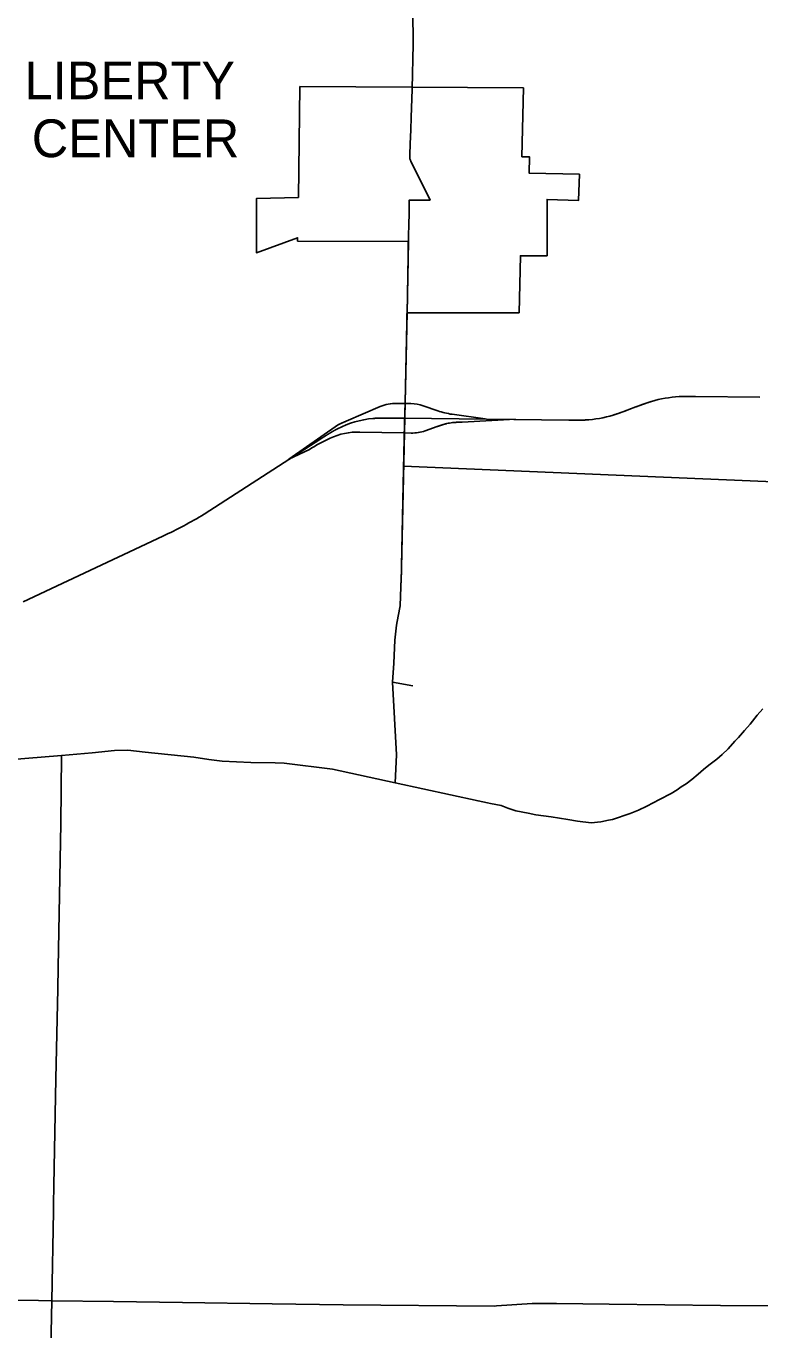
# Model space of a CAD drawing. Extents: x -62 to 810, y 0 to 440.
# Drawn here: x 358.3 to 408.1, y 261.1 to 349.6 of the extents above; entities that cross this region are included whole.
import ezdxf

# ---------------------------------------------------------------- set-up
doc = ezdxf.new("R2010")
doc.units = 0
for name, color, linetype in [('DV_X_Corp_Line', 7, 'Continuous'), ('GM_X_Corporation_Text', 7, 'Continuous'), ('GM_X_State_Route', 7, 'Continuous'), ('SH_Data', 7, 'Continuous'), ('SH_Text', 7, 'Continuous')]:
    doc.layers.add(name, color=color, linetype=linetype)

msp = doc.modelspace()

# ---------------------------------------------------------------- linework, layer by layer
at = {"layer": 'DV_X_Corp_Line'}
msp.add_lwpolyline([(376.707, 335.035), (376.714, 335.257), (373.916, 334.245), (373.932, 337.925), (376.768, 337.998), (376.868, 345.517), (392.056, 345.433), (391.959, 340.759), (392.478, 340.748), (392.455, 339.639), (395.861, 339.566), (395.808, 337.796), (393.665, 337.864), (393.664, 334.036), (391.854, 334.033), (391.762, 330.17), (384.151, 330.165), (384.247, 334.998)], close=True, dxfattribs=at)
at = {"layer": 'GM_X_State_Route'}
for p, q in [((383.455, 324.016), (383.975, 324.006)), ((383.975, 324.006), (384.416, 323.997)), ((403.764, 324.485), (408.134, 324.432)), ((380.022, 322.81), (382.331, 323.797)), ((385.238, 323.853), (386.235, 323.514)), ((389.467, 322.957), (387.217, 323.272)), ((399.222, 323.592), (399.69, 323.769)), ((376.124, 320.23), (379.501, 322.578)), ((383.956, 323.009), (395.151, 322.875)), ((385.378, 322.152), (386.208, 322.441)), ((387.908, 322.736), (391.52, 322.937)), ((370.359, 316.484), (378.304, 321.613)), ((380.948, 322.07), (383.934, 322.011)), ((383.934, 322.011), (384.43, 322.002)), ((377.523, 320.881), (376.124, 320.23)), ((358.077, 310.544), (367.562, 315)), ((384.536, 304.847), (383.167, 305.08))]:
    msp.add_line(p, q, dxfattribs=at)
for points in [[(384.503, 345.373), (384.58, 348.411), (384.534, 352.965), (384.815, 368.019), (385.213, 389.406)], [(384.381, 340.524), (384.377, 340.535), (384.339, 340.625), (384.34, 340.882), (384.368, 341.642), (384.402, 342.577), (384.433, 343.44), (384.502, 345.322), (384.503, 345.373)], [(385.724, 337.8), (385.724, 337.8), (385.106, 339.053), (384.8, 339.673), (384.417, 340.449), (384.387, 340.509), (384.381, 340.524)], [(384.24, 334.635), (384.286, 336.915), (384.304, 337.821), (385.724, 337.8)], [(384.228, 334.029), (384.229, 334.113), (384.24, 334.635)], [(384.173, 331.298), (384.175, 331.39), (384.228, 334.029)], [(384.149, 330.085), (384.151, 330.179), (384.173, 331.298)], [(383.742, 311.819), (383.743, 311.857), (383.899, 318.509), (383.985, 322.653), (384, 323.397), (384.014, 324.054), (384.138, 329.513), (384.149, 330.085)], [(383.167, 305.08), (383.244, 306.376), (383.331, 307.934), (383.433, 308.966), (383.557, 309.562), (383.679, 310.268), (383.736, 311.569), (383.742, 311.819)], [(383.348, 298.264), (383.438, 300.159), (383.167, 305.08)], [(389.833, 296.853), (390.541, 296.707), (390.994, 296.536), (391.545, 296.348), (392.375, 296.186), (392.916, 296.08), (393.942, 295.943), (395.089, 295.763), (395.728, 295.658), (396.671, 295.54), (397.316, 295.608), (397.843, 295.72), (398.104, 295.775), (399.32, 296.172), (399.877, 296.409), (400.452, 296.68), (400.889, 296.896), (401.31, 297.112), (402.111, 297.529), (402.511, 297.769), (402.79, 297.974), (403.125, 298.187), (403.495, 298.484), (403.928, 298.843), (404.305, 299.163), (404.663, 299.46), (405.201, 299.869), (405.571, 300.183), (405.965, 300.571), (406.436, 301.09), (406.668, 301.326), (407.093, 301.817), (407.465, 302.245), (407.937, 302.849), (408.337, 303.272)], [(350.801, 300.622), (353.067, 300.321), (354.335, 300.101), (355.937, 299.736), (360.668, 300.11)], [(360.148, 270.819), (360.15, 270.917), (360.194, 273.339), (360.278, 278.152), (360.43, 284.278), (360.455, 285.73), (360.627, 295.47), (360.668, 300.11)], [(360.668, 300.11), (362.765, 300.302), (364.263, 300.439), (365.182, 300.461), (366.363, 300.347), (369.655, 300.006), (370.694, 299.838), (371.587, 299.714), (373.541, 299.642), (375.195, 299.607), (375.808, 299.587), (379.079, 299.172), (383.348, 298.264)], [(383.348, 298.264), (388.985, 297.028), (389.613, 296.898), (389.833, 296.853)], [(360.118, 269.153), (360.12, 269.262), (360.126, 269.596), (360.128, 269.733), (360.148, 270.819)], [(360.007, 263.095), (360.118, 269.153)], [(355.008, 263.139), (355.055, 263.138), (359.098, 263.103)], [(359.098, 263.103), (359.106, 263.103), (360.007, 263.095)], [(359.66, 220.968), (359.691, 227.727), (359.734, 232.912), (359.691, 233.115), (359.617, 233.258), (359.542, 233.389), (359.497, 233.555), (359.48, 233.903), (359.693, 247.954), (359.849, 255.51), (360.007, 263.095)], [(360.007, 263.095), (364.198, 263.037)], [(364.198, 263.037), (368.891, 262.972), (374.978, 262.881), (379.814, 262.808), (390.079, 262.732), (390.242, 262.754), (392.655, 262.906), (393.215, 262.916), (394.306, 262.896), (397.877, 262.859), (405.457, 262.782), (408.703, 262.749), (413.048, 262.725), (420.595, 262.684), (425.883, 262.655), (429.596, 262.616), (429.597, 262.616)]]:
    msp.add_lwpolyline(points, dxfattribs=at)
for centre, radius, start, end in [((383.401, 321.295), 2.722, 88.87, 113.16335), ((384.363, 321.276), 2.722, 71.23123, 88.87), ((403.1, 316.322), 8.165, 93.2557, 106.69439), ((388.141, 329.123), 5.924, 251.23123, 261.02199), ((395.812, 331.039), 8.165, 273.27836, 286.69439), ((382.419, 316.484), 6.532, 95.09336, 117.22501), ((387.6, 319.462), 3.266, 96.33912, 103.32164), ((383.452, 311.751), 10.886, 114.61118, 123.00153), ((380.856, 317.419), 4.653, 88.87, 114.61118), ((384.484, 324.72), 2.719, 268.87, 289.19664), ((353.674, 344.559), 32.659, 295.16667, 300.72373)]:
    msp.add_arc(centre, radius, start, end, dxfattribs=at)
for points in [[(399.69, 323.769), (399.704, 323.774), (399.718, 323.779), (399.732, 323.785), (399.747, 323.79), (399.761, 323.795), (399.775, 323.801), (399.79, 323.806), (399.804, 323.812), (399.818, 323.817), (399.832, 323.822), (399.847, 323.828), (399.861, 323.833), (399.875, 323.838), (399.889, 323.844), (399.904, 323.849), (399.918, 323.854), (399.932, 323.86), (399.947, 323.865), (399.961, 323.87), (399.975, 323.876), (399.99, 323.881), (400.004, 323.886), (400.018, 323.892), (400.032, 323.897), (400.047, 323.902), (400.061, 323.907), (400.075, 323.913), (400.09, 323.918), (400.104, 323.923), (400.118, 323.928), (400.133, 323.934), (400.147, 323.939), (400.161, 323.944), (400.176, 323.949), (400.19, 323.954), (400.204, 323.959), (400.219, 323.965), (400.233, 323.97), (400.248, 323.975), (400.262, 323.98), (400.276, 323.985), (400.291, 323.99), (400.305, 323.995), (400.319, 324), (400.334, 324.005), (400.348, 324.01), (400.363, 324.015), (400.377, 324.02), (400.391, 324.025), (400.406, 324.03), (400.42, 324.035), (400.435, 324.04), (400.449, 324.045), (400.464, 324.05), (400.478, 324.054), (400.493, 324.059), (400.507, 324.064), (400.522, 324.069), (400.536, 324.074), (400.551, 324.078), (400.565, 324.083), (400.58, 324.088), (400.594, 324.092), (400.609, 324.097), (400.623, 324.102), (400.638, 324.106), (400.652, 324.111), (400.667, 324.115), (400.681, 324.12), (400.696, 324.124), (400.711, 324.129), (400.725, 324.133), (400.74, 324.138), (400.754, 324.142)], [(402.636, 324.473), (402.651, 324.474), (402.667, 324.475), (402.682, 324.476), (402.697, 324.476), (402.712, 324.477), (402.727, 324.478), (402.743, 324.478), (402.758, 324.479), (402.773, 324.48), (402.788, 324.48), (402.804, 324.481), (402.819, 324.482), (402.834, 324.482), (402.849, 324.483), (402.865, 324.483), (402.88, 324.484), (402.895, 324.484), (402.91, 324.484), (402.926, 324.485), (402.941, 324.485), (402.956, 324.486), (402.971, 324.486), (402.987, 324.486), (403.002, 324.487), (403.017, 324.487), (403.032, 324.487), (403.048, 324.487), (403.063, 324.488), (403.078, 324.488), (403.093, 324.488), (403.109, 324.488), (403.124, 324.488), (403.139, 324.488), (403.154, 324.489), (403.17, 324.489), (403.185, 324.489), (403.2, 324.489), (403.215, 324.489), (403.231, 324.489), (403.246, 324.489), (403.261, 324.489), (403.276, 324.489), (403.292, 324.489), (403.307, 324.489), (403.322, 324.489), (403.337, 324.489), (403.353, 324.489), (403.368, 324.489), (403.383, 324.489), (403.398, 324.489), (403.414, 324.489), (403.429, 324.489), (403.444, 324.489), (403.459, 324.488), (403.475, 324.488), (403.49, 324.488), (403.505, 324.488), (403.52, 324.488), (403.536, 324.488), (403.551, 324.488), (403.566, 324.488), (403.581, 324.487), (403.597, 324.487), (403.612, 324.487), (403.627, 324.487), (403.642, 324.487), (403.658, 324.487), (403.673, 324.486), (403.688, 324.486), (403.703, 324.486), (403.719, 324.486), (403.734, 324.486), (403.749, 324.485), (403.764, 324.485)], [(398.158, 323.219), (398.172, 323.223), (398.187, 323.228), (398.201, 323.232), (398.216, 323.237), (398.23, 323.241), (398.245, 323.246), (398.26, 323.25), (398.274, 323.255), (398.289, 323.259), (398.303, 323.264), (398.318, 323.269), (398.332, 323.273), (398.347, 323.278), (398.361, 323.283), (398.376, 323.287), (398.39, 323.292), (398.405, 323.297), (398.419, 323.302), (398.434, 323.307), (398.448, 323.311), (398.463, 323.316), (398.477, 323.321), (398.491, 323.326), (398.506, 323.331), (398.52, 323.336), (398.535, 323.341), (398.549, 323.346), (398.564, 323.351), (398.578, 323.356), (398.592, 323.361), (398.607, 323.366), (398.621, 323.371), (398.636, 323.376), (398.65, 323.381), (398.664, 323.386), (398.679, 323.391), (398.693, 323.396), (398.707, 323.402), (398.722, 323.407), (398.736, 323.412), (398.75, 323.417), (398.765, 323.422), (398.779, 323.427), (398.794, 323.433), (398.808, 323.438), (398.822, 323.443), (398.836, 323.448), (398.851, 323.454), (398.865, 323.459), (398.879, 323.464), (398.894, 323.469), (398.908, 323.475), (398.922, 323.48), (398.937, 323.485), (398.951, 323.491), (398.965, 323.496), (398.98, 323.501), (398.994, 323.507), (399.008, 323.512), (399.022, 323.517), (399.037, 323.523), (399.051, 323.528), (399.065, 323.533), (399.08, 323.539), (399.094, 323.544), (399.108, 323.549), (399.122, 323.555), (399.137, 323.56), (399.151, 323.566), (399.165, 323.571), (399.179, 323.576), (399.194, 323.582), (399.208, 323.587), (399.222, 323.592)], [(378.304, 321.613), (378.318, 321.622), (378.333, 321.632), (378.348, 321.642), (378.363, 321.651), (378.378, 321.661), (378.393, 321.671), (378.408, 321.68), (378.423, 321.69), (378.438, 321.7), (378.453, 321.709), (378.468, 321.719), (378.483, 321.729), (378.498, 321.738), (378.513, 321.748), (378.528, 321.758), (378.543, 321.767), (378.557, 321.777), (378.572, 321.786), (378.587, 321.796), (378.602, 321.806), (378.617, 321.815), (378.632, 321.825), (378.647, 321.834), (378.662, 321.844), (378.678, 321.853), (378.693, 321.863), (378.708, 321.872), (378.723, 321.882), (378.738, 321.891), (378.753, 321.901), (378.768, 321.91), (378.783, 321.92), (378.798, 321.929), (378.813, 321.938), (378.828, 321.948), (378.843, 321.957), (378.859, 321.966), (378.874, 321.976), (378.889, 321.985), (378.904, 321.994), (378.919, 322.003), (378.935, 322.013), (378.95, 322.022), (378.965, 322.031), (378.98, 322.04), (378.996, 322.049), (379.011, 322.058), (379.026, 322.067), (379.042, 322.076), (379.057, 322.086), (379.072, 322.094), (379.088, 322.103), (379.103, 322.112), (379.118, 322.121), (379.134, 322.13), (379.149, 322.139), (379.165, 322.148), (379.18, 322.157), (379.196, 322.165), (379.211, 322.174), (379.227, 322.183), (379.242, 322.191), (379.258, 322.2), (379.274, 322.208), (379.289, 322.217), (379.305, 322.225), (379.321, 322.234), (379.336, 322.242), (379.352, 322.251), (379.368, 322.259), (379.383, 322.267), (379.399, 322.275), (379.415, 322.284), (379.431, 322.292)], [(379.501, 322.578), (379.508, 322.582), (379.515, 322.585), (379.522, 322.588), (379.529, 322.592), (379.536, 322.595), (379.543, 322.598), (379.55, 322.601), (379.557, 322.605), (379.564, 322.608), (379.571, 322.611), (379.578, 322.614), (379.585, 322.618), (379.592, 322.621), (379.599, 322.624), (379.606, 322.627), (379.613, 322.631), (379.62, 322.634), (379.627, 322.637), (379.634, 322.64), (379.641, 322.643), (379.648, 322.647), (379.655, 322.65), (379.662, 322.653), (379.669, 322.656), (379.676, 322.659), (379.683, 322.662), (379.69, 322.666), (379.697, 322.669), (379.704, 322.672), (379.711, 322.675), (379.718, 322.678), (379.725, 322.681), (379.732, 322.684), (379.74, 322.687), (379.747, 322.691), (379.754, 322.694), (379.761, 322.697), (379.768, 322.7), (379.775, 322.703), (379.782, 322.706), (379.789, 322.709), (379.796, 322.712), (379.803, 322.715), (379.81, 322.718), (379.817, 322.722), (379.824, 322.725), (379.831, 322.728), (379.838, 322.731), (379.845, 322.734), (379.852, 322.737), (379.86, 322.74), (379.867, 322.743), (379.874, 322.746), (379.881, 322.749), (379.888, 322.752), (379.895, 322.755), (379.902, 322.758), (379.909, 322.761), (379.916, 322.764), (379.923, 322.767), (379.93, 322.77), (379.937, 322.773), (379.944, 322.776), (379.951, 322.78), (379.959, 322.783), (379.966, 322.786), (379.973, 322.789), (379.98, 322.792), (379.987, 322.795), (379.994, 322.798), (380.001, 322.801), (380.008, 322.804), (380.015, 322.807), (380.022, 322.81)], [(381.839, 322.99), (381.857, 322.991), (381.874, 322.993), (381.892, 322.994), (381.91, 322.996), (381.928, 322.997), (381.945, 322.998), (381.963, 323), (381.981, 323.001), (381.999, 323.002), (382.016, 323.003), (382.034, 323.004), (382.052, 323.005), (382.07, 323.006), (382.088, 323.007), (382.105, 323.008), (382.123, 323.009), (382.141, 323.01), (382.159, 323.011), (382.176, 323.012), (382.194, 323.012), (382.212, 323.013), (382.23, 323.014), (382.247, 323.015), (382.265, 323.015), (382.283, 323.016), (382.301, 323.016), (382.319, 323.017), (382.336, 323.017), (382.354, 323.018), (382.372, 323.018), (382.39, 323.019), (382.408, 323.019), (382.425, 323.019), (382.443, 323.02), (382.461, 323.02), (382.479, 323.02), (382.497, 323.02), (382.514, 323.021), (382.532, 323.021), (382.55, 323.021), (382.568, 323.021), (382.585, 323.021), (382.603, 323.022), (382.621, 323.022), (382.639, 323.022), (382.657, 323.022), (382.674, 323.022), (382.692, 323.022), (382.71, 323.022), (382.728, 323.022), (382.746, 323.022), (382.763, 323.022), (382.781, 323.022), (382.799, 323.022), (382.817, 323.021), (382.835, 323.021), (382.852, 323.021), (382.87, 323.021), (382.888, 323.021), (382.906, 323.021), (382.924, 323.021), (382.941, 323.021), (382.959, 323.02), (382.977, 323.02), (382.995, 323.02), (383.012, 323.02), (383.03, 323.02), (383.048, 323.019), (383.066, 323.019), (383.084, 323.019), (383.101, 323.019), (383.119, 323.019), (383.137, 323.018), (383.155, 323.018), (383.956, 323.009)], [(386.208, 322.441), (386.217, 322.444), (386.225, 322.447), (386.234, 322.45), (386.242, 322.453), (386.251, 322.456), (386.259, 322.459), (386.268, 322.462), (386.277, 322.465), (386.285, 322.468), (386.294, 322.471), (386.302, 322.474), (386.311, 322.477), (386.319, 322.48), (386.328, 322.483), (386.336, 322.486), (386.345, 322.489), (386.354, 322.492), (386.362, 322.495), (386.371, 322.498), (386.379, 322.5), (386.388, 322.503), (386.396, 322.506), (386.405, 322.509), (386.414, 322.512), (386.422, 322.515), (386.431, 322.518), (386.439, 322.521), (386.448, 322.524), (386.456, 322.526), (386.465, 322.529), (386.474, 322.532), (386.482, 322.535), (386.491, 322.538), (386.499, 322.54), (386.508, 322.543), (386.517, 322.546), (386.525, 322.549), (386.534, 322.552), (386.543, 322.554), (386.551, 322.557), (386.56, 322.56), (386.568, 322.562), (386.577, 322.565), (386.586, 322.568), (386.594, 322.57), (386.603, 322.573), (386.612, 322.576), (386.62, 322.578), (386.629, 322.581), (386.638, 322.583), (386.646, 322.586), (386.655, 322.589), (386.664, 322.591), (386.673, 322.594), (386.681, 322.596), (386.69, 322.599), (386.699, 322.601), (386.707, 322.604), (386.716, 322.606), (386.725, 322.608), (386.734, 322.611), (386.742, 322.613), (386.751, 322.615), (386.76, 322.618), (386.768, 322.62), (386.777, 322.622), (386.786, 322.625), (386.795, 322.627), (386.804, 322.629), (386.812, 322.631), (386.821, 322.633), (386.83, 322.636), (386.839, 322.638), (386.848, 322.64)], [(387.239, 322.708), (387.248, 322.709), (387.257, 322.71), (387.266, 322.711), (387.275, 322.711), (387.284, 322.712), (387.293, 322.713), (387.302, 322.714), (387.311, 322.715), (387.321, 322.716), (387.33, 322.716), (387.339, 322.717), (387.348, 322.718), (387.357, 322.719), (387.366, 322.719), (387.375, 322.72), (387.384, 322.721), (387.393, 322.721), (387.402, 322.722), (387.411, 322.723), (387.42, 322.723), (387.429, 322.724), (387.438, 322.724), (387.447, 322.725), (387.456, 322.725), (387.465, 322.726), (387.474, 322.726), (387.483, 322.727), (387.492, 322.727), (387.501, 322.728), (387.51, 322.728), (387.519, 322.728), (387.528, 322.729), (387.537, 322.729), (387.546, 322.729), (387.555, 322.73), (387.564, 322.73), (387.573, 322.73), (387.583, 322.731), (387.592, 322.731), (387.601, 322.731), (387.61, 322.732), (387.619, 322.732), (387.628, 322.732), (387.637, 322.732), (387.646, 322.732), (387.655, 322.733), (387.664, 322.733), (387.673, 322.733), (387.682, 322.733), (387.691, 322.733), (387.7, 322.734), (387.709, 322.734), (387.718, 322.734), (387.727, 322.734), (387.736, 322.734), (387.745, 322.734), (387.754, 322.734), (387.763, 322.735), (387.773, 322.735), (387.782, 322.735), (387.791, 322.735), (387.8, 322.735), (387.809, 322.735), (387.818, 322.735), (387.827, 322.735), (387.836, 322.735), (387.845, 322.735), (387.854, 322.736), (387.863, 322.736), (387.872, 322.736), (387.881, 322.736), (387.89, 322.736), (387.899, 322.736), (387.908, 322.736)], [(395.151, 322.875), (395.166, 322.875), (395.181, 322.875), (395.196, 322.875), (395.212, 322.875), (395.227, 322.875), (395.242, 322.874), (395.257, 322.874), (395.273, 322.874), (395.288, 322.874), (395.303, 322.874), (395.318, 322.874), (395.334, 322.873), (395.349, 322.873), (395.364, 322.873), (395.379, 322.873), (395.395, 322.873), (395.41, 322.873), (395.425, 322.873), (395.44, 322.872), (395.456, 322.872), (395.471, 322.872), (395.486, 322.872), (395.501, 322.872), (395.517, 322.872), (395.532, 322.872), (395.547, 322.872), (395.562, 322.872), (395.578, 322.872), (395.593, 322.872), (395.608, 322.872), (395.623, 322.872), (395.639, 322.872), (395.654, 322.872), (395.669, 322.872), (395.684, 322.872), (395.7, 322.872), (395.715, 322.872), (395.73, 322.872), (395.745, 322.872), (395.761, 322.872), (395.776, 322.872), (395.791, 322.873), (395.807, 322.873), (395.822, 322.873), (395.837, 322.873), (395.852, 322.873), (395.868, 322.874), (395.883, 322.874), (395.898, 322.874), (395.913, 322.874), (395.928, 322.875), (395.944, 322.875), (395.959, 322.875), (395.974, 322.876), (395.989, 322.876), (396.005, 322.877), (396.02, 322.877), (396.035, 322.877), (396.05, 322.878), (396.066, 322.878), (396.081, 322.879), (396.096, 322.88), (396.111, 322.88), (396.127, 322.881), (396.142, 322.881), (396.157, 322.882), (396.172, 322.883), (396.188, 322.883), (396.203, 322.884), (396.218, 322.885), (396.233, 322.886), (396.249, 322.886), (396.264, 322.887), (396.279, 322.888)]]:
    msp.add_spline(points, degree=3, dxfattribs=at)
at = {"layer": 'SH_Data'}
msp.add_line((488.427, 315.399), (383.919, 319.743), dxfattribs=at)
at = {"layer": 'SH_Text'}
msp.add_line((383.743, 311.857), (384.151, 330.179), dxfattribs=at)

# ---------------------------------------------------------------- texts
at = {"layer": 'GM_X_Corporation_Text'}
for s, p in [('LIBERTY', (358.166, 344.657)), ('CENTER', (358.652, 340.728))]:
    msp.add_text(s, height=2.565, rotation=0.00001, dxfattribs=at).set_placement(p)

doc.saveas('drawing.dxf')
